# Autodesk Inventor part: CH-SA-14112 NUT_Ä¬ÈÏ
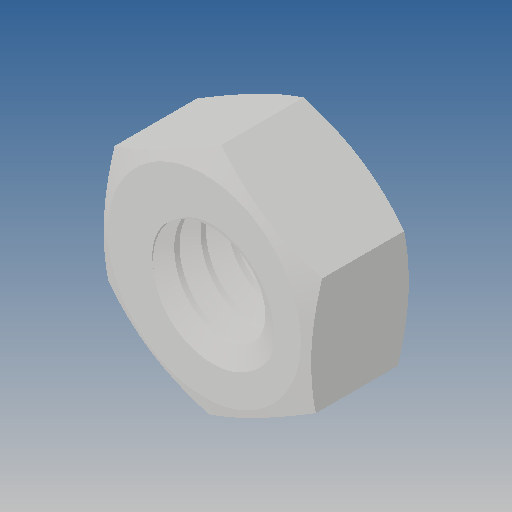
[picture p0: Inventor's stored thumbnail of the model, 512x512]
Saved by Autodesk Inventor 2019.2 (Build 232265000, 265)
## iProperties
Created: 2010-06
Part Number: CH-SA-14112 NUT_Ä¬ÈÏ
Material: Ogólny
Document SubType Name: Modeling
Designer: CADENGINEERING4
Density: 1 g/cm^3
Appearance: Domyślna
Author: CADENGINEERING4
Revision Number: ÈÎºÎ
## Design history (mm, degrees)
feature "NONE"
node "Bryła1"
